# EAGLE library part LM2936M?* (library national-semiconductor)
Ultra-Low Quiescent Current LDO Voltage Regulator Source: Data sheet
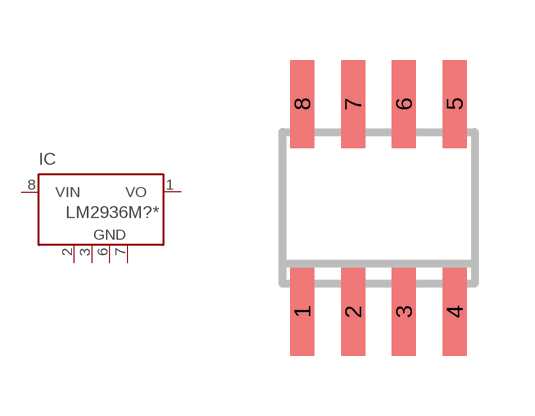
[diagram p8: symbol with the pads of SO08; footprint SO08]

Designator prefix IC

## LM2936M-3.0 (OC_FARNELL: 1286868; OC_NEWARK: unknown), LM2936M-3.3 (MF: NATIONAL SEMICONDUCTOR; MPN: LM2936M-3.3/NOPB; OC_FARNELL: 1469059; OC_NEWARK: 41K4514), LM2936M-5.0 (MF: NATIONAL SEMICONDUCTOR; MPN: LM2936M-5.0/NOPB; OC_FARNELL: 9494421; OC_NEWARK: 41K4515)  [SO08]
1  VO  pas
2  GND  pas
3  GND  pas
6  GND  pas
7  GND  pas
8  VIN  in

## Footprint SO08 (pad centres in mm)
Small Outline Package 8 NS Package M08A
smd 0.6 x 2.2: 1 -1.905,-2.6; 2 -0.635,-2.6; 3 0.635,-2.6; 4 1.905,-2.6; 5 1.905,2.6; 6 0.635,2.6; 7 -0.635,2.6; 8 -1.905,2.6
